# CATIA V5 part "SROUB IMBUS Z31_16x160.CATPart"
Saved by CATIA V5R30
Part number: SROUB IMBUS Z31/16x160
Bounding box of the stored display mesh (mm): x -16 to 160, y -11.99 to 11.99, z -12 to 12
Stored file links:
  C:\Users\ondra\Desktop\PŘÍLOHA P III\CATIA\SROUB IMBUS Z31_16x160.CATPart
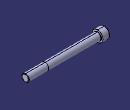
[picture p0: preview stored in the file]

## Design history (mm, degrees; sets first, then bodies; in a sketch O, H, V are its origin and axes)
Set1
  DatumSurface1 to DatumSurface30 "Z31/16x1"
  Join1: Elements (DatumSurface1; DatumSurface2; DatumSurface3; DatumSurface4; DatumSurface5; DatumSurface6; DatumSurface7; DatumSurface8; DatumSurface9; DatumSurface10; DatumSurface11; DatumSurface12; DatumSurface13; DatumSurface14; DatumSurface16; DatumSurface17; DatumSurface18; DatumSurface19; DatumSurface20; DatumSurface21; DatumSurface22; DatumSurface23; DatumSurface24; DatumSurface25; DatumSurface26; DatumSurface27; DatumSurface28; DatumSurface29; DatumSurface30)
Body1 (main body)
  CloseSurface1: CloseElement Join1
